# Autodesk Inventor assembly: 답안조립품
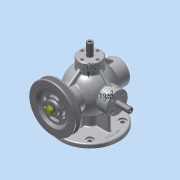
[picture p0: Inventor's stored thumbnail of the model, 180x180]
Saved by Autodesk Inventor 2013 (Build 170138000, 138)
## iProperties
Created: 2016-07
Part Number: 답안조립품
Document SubType Name: Assembly
Designer: dgall
Mass: 3970.14 g
Surface Area: 2574.68 cm^2
Volume: 982.855 cm^3
Density: 4.03939 g/cm^3
Author: dgall
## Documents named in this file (17)
- C:\Users\dgall\Desktop\360707V1024\답안조립품.iam
- C:\Users\dgall\Desktop\360707V1024\본체.ipt
- C:\Users\dgall\Desktop\360707V1024\본체커버.ipt
- C:\Users\dgall\Desktop\360707V1024\베어링- 6202.ipt
- C:\Users\dgall\Desktop\360707V1024\앞커버.ipt
- C:\Users\dgall\Desktop\360707V1024\뒤커버.ipt
- C:\Users\dgall\Desktop\360707V1024\슬라이드 커버.ipt
- C:\Users\dgall\Desktop\360707V1024\축.ipt
- C:\Users\dgall\Desktop\360707V1024\오일실.ipt
- C:\Users\dgall\Desktop\360707V1024\키-4x4.ipt
- C:\Users\dgall\Desktop\360707V1024\V-벨트풀리.ipt
- C:\Users\dgall\Desktop\360707V1024\와셔 8x17.ipt
- C:\Users\dgall\Desktop\360707V1024\너트-M8x1.ipt
- C:\Users\dgall\Desktop\360707V1024\볼트 M4x0.7.ipt
- C:\Users\dgall\Desktop\360707V1024\슬라이드.ipt
- C:\Users\dgall\Desktop\360707V1024\스프링1.ipt
- C:\Users\dgall\Desktop\360707V1024\스프링2.ipt
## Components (18 placed, 2 different names)
1. V-벨트풀리:1 — 플러쉬:2
2. M4x0.7x12:1
3. M4x0.7x12:3
4. M4x0.7x12:6
5. M4x0.7x12:7
6. M4x0.7x12:8
7. M4x0.7x12:4
8. M4x0.7x12:9
9. M4x0.7x12:10
10. M4x0.7x12:11
11. M4x0.7x12:5
12. M4x0.7x12:12
13. M4x0.7x12:13
14. M4x0.7x12:14
15. M4x0.7x12:2
16. M4x0.7x12:15
17. M4x0.7x12:16
18. M4x0.7x12:17
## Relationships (1: Flush 1)
- 플러쉬:2 [Flush]: V-벨트풀리:1
